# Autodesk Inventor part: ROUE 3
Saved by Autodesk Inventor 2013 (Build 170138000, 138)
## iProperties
Created: 2012-12
Part Number: ROUE 3
Material: Générique
Document SubType Name: Modeling
Designer: jost thierry
Density: 1 g/cm^3
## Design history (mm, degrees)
node "ROUE 31"
node "ROUE 3"
node "Base1"
